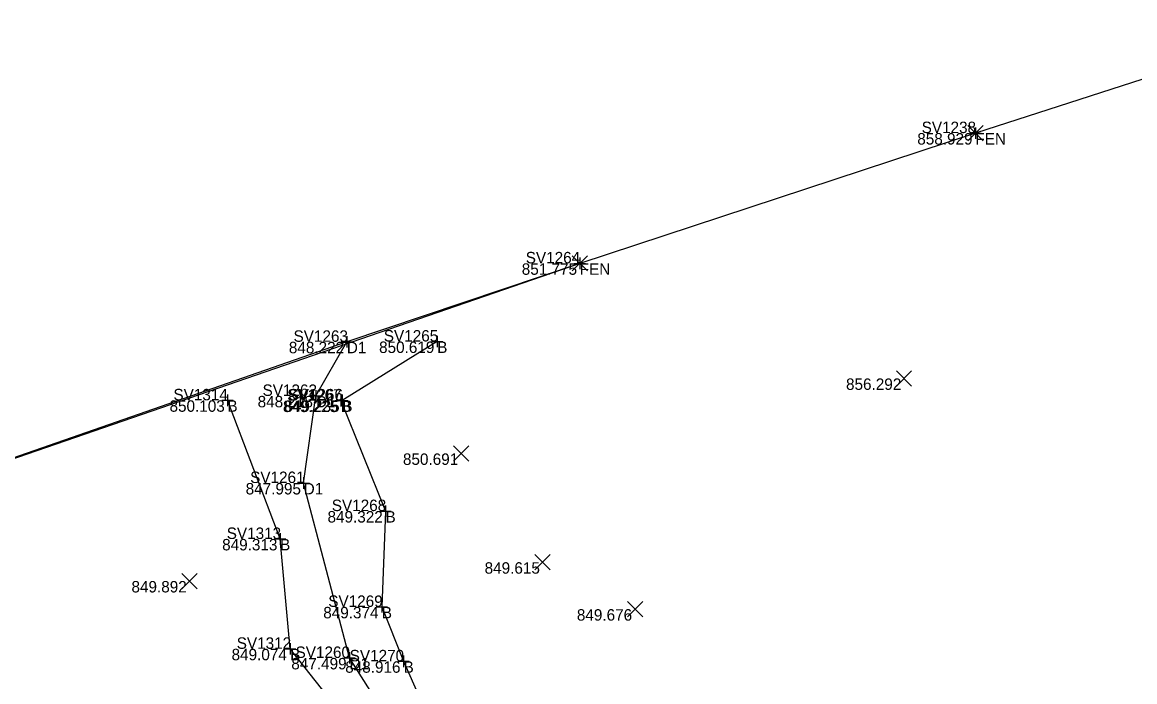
# Model space of a CAD drawing. Extents: x 2125299 to 2129212, y 713100 to 714300.
# Drawn here: x 2128258.4 to 2128355.7, y 714191.5 to 714249.1 of the extents above; entities that cross this region are included whole.
import ezdxf

# ---------------------------------------------------------------- set-up
doc = ezdxf.new("R2010")
doc.units = 0
for name, color, linetype in [('DR_X_Ditch', 7, 'Continuous'), ('DT_X_Terrain_Boundary', 7, 'Continuous'), ('RD_X_Fence', 7, 'Continuous'), ('RW_P_Esmt_TMP', 7, 'Continuous'), ('RW_X_Esmt_CH', 7, 'Continuous'), ('RW_X_Fee_WL', 7, 'Continuous'), ('SV_X_Break_Lines', 7, 'Continuous'), ('SV_X_Mon_Cells_Found', 7, 'Continuous'), ('SV_X_Text_Elevation', 7, 'Continuous')]:
    doc.layers.add(name, color=color, linetype=linetype)

msp = doc.modelspace()

# ---------------------------------------------------------------- linework, layer by layer
at = {"layer": 'DR_X_Ditch'}
msp.add_lwpolyline([(2128282.878, 714152.985), (2128282.322, 714154.568), (2128280.684, 714162.784), (2128280.715, 714165.854), (2128282.282, 714171.907), (2128284.07, 714176.901), (2128291.608, 714180.596), (2128291.656, 714186.324), (2128287.057, 714193.601), (2128283.052, 714208.887), (2128284.129, 714216.499), (2128286.829, 714221.225)], dxfattribs=at)
at = {"layer": 'DT_X_Terrain_Boundary'}
msp.add_lwpolyline([(2128442.631, 714160.201), (2128404.428, 714186.272), (2128371.881, 714249.149), (2128341.796, 714239.463), (2128307.194, 714228.082), (2128286.829, 714221.225), (2128228.864, 714201.068), (2128207.391, 714193.903), (2128150.546, 714124.176), (2128126.019, 714119.425), (2128120.141, 714107.516), (2128111.883, 714086.218), (2128106.869, 714068.79), (2128101.835, 714061.266), (2128102.404, 714047.835), (2128092.731, 714045.299), (2128083.057, 714042.765), (2128073.384, 714040.23), (2128063.71, 714037.696), (2128054.037, 714035.161), (2128044.363, 714032.627), (2128034.69, 714030.093), (2128025.016, 714027.558)], dxfattribs=at)
at = {"layer": 'RD_X_Fence'}
msp.add_lwpolyline([(2128371.881, 714249.149), (2128341.796, 714239.463), (2128307.194, 714228.082), (2128228.863, 714201.068), (2128207.391, 714193.903)], dxfattribs=at)
at = {"layer": 'SV_X_Break_Lines'}
for points in [[(2128294.731, 714221.25), (2128286.429, 714216.107), (2128286.307, 714216.085), (2128290.211, 714206.434), (2128289.886, 714198.061), (2128291.79, 714193.305), (2128293.753, 714188.829), (2128301.414, 714189.738), (2128311.099, 714187.98), (2128315.392, 714186.993), (2128315.738, 714184.367), (2128308.586, 714184.286), (2128301.154, 714185.129), (2128295.038, 714185.419), (2128293.414, 714179.277), (2128290.994, 714176.583), (2128286.414, 714175.49), (2128286.417, 714175.493), (2128286.617, 714173.173), (2128291.92, 714175.499), (2128298.034, 714172.742), (2128324.661, 714177.129), (2128340.162, 714175.773), (2128345.323, 714175.683)], [(2128281.871, 714194.398), (2128280.987, 714203.998), (2128276.385, 714216.113)], [(2128279.118, 714167.221), (2128278.774, 714174.351), (2128283.748, 714179.208), (2128288.829, 714182.513), (2128286.358, 714188.724), (2128281.871, 714194.398)]]:
    msp.add_lwpolyline(points, dxfattribs=at)
at = {"layer": 'SV_X_Mon_Cells_Found'}
for p, q in [((2128341.796, 714239.963), (2128341.796, 714238.963)), ((2128341.296, 714239.463), (2128342.296, 714239.463)), ((2128341.796, 714239.463), (2128341.796, 714239.463)), ((2128307.194, 714228.582), (2128307.194, 714227.582)), ((2128306.694, 714228.082), (2128307.694, 714228.082)), ((2128307.194, 714228.082), (2128307.194, 714228.082)), ((2128286.829, 714221.725), (2128286.829, 714220.725)), ((2128294.731, 714221.75), (2128294.731, 714220.75)), ((2128286.329, 714221.225), (2128287.329, 714221.225)), ((2128286.829, 714221.225), (2128286.829, 714221.225)), ((2128294.231, 714221.25), (2128295.231, 714221.25)), ((2128294.731, 714221.25), (2128294.731, 714221.25)), ((2128276.385, 714216.613), (2128276.385, 714215.613)), ((2128284.129, 714216.999), (2128284.129, 714215.999)), ((2128286.307, 714216.585), (2128286.307, 714215.585)), ((2128286.429, 714216.607), (2128286.429, 714215.607)), ((2128275.885, 714216.113), (2128276.885, 714216.113)), ((2128276.385, 714216.113), (2128276.385, 714216.113)), ((2128283.629, 714216.499), (2128284.629, 714216.499)), ((2128284.129, 714216.499), (2128284.129, 714216.499)), ((2128285.807, 714216.085), (2128286.807, 714216.085)), ((2128285.929, 714216.107), (2128286.929, 714216.107)), ((2128286.307, 714216.085), (2128286.307, 714216.085)), ((2128286.429, 714216.107), (2128286.429, 714216.107)), ((2128282.552, 714208.887), (2128283.552, 714208.887)), ((2128283.052, 714209.387), (2128283.052, 714208.387)), ((2128283.052, 714208.887), (2128283.052, 714208.887)), ((2128290.211, 714206.934), (2128290.211, 714205.934)), ((2128289.711, 714206.434), (2128290.711, 714206.434)), ((2128290.211, 714206.434), (2128290.211, 714206.434)), ((2128280.487, 714203.998), (2128281.487, 714203.998)), ((2128280.987, 714204.498), (2128280.987, 714203.498)), ((2128280.987, 714203.998), (2128280.987, 714203.998)), ((2128289.886, 714198.561), (2128289.886, 714197.561)), ((2128289.386, 714198.061), (2128290.386, 714198.061)), ((2128289.886, 714198.061), (2128289.886, 714198.061)), ((2128281.371, 714194.398), (2128282.371, 714194.398)), ((2128281.871, 714194.898), (2128281.871, 714193.898)), ((2128281.871, 714194.398), (2128281.871, 714194.398)), ((2128286.557, 714193.601), (2128287.557, 714193.601)), ((2128287.057, 714194.101), (2128287.057, 714193.101)), ((2128287.057, 714193.601), (2128287.057, 714193.601)), ((2128291.29, 714193.305), (2128292.29, 714193.305)), ((2128291.79, 714193.805), (2128291.79, 714192.805)), ((2128291.79, 714193.305), (2128291.79, 714193.305))]:
    msp.add_line(p, q, dxfattribs=at)
at = {"layer": 'SV_X_Text_Elevation'}
for p, q in [((2128341.129, 714238.795), (2128342.463, 714240.13)), ((2128341.129, 714240.13), (2128342.463, 714238.795)), ((2128306.527, 714227.415), (2128307.861, 714228.75)), ((2128306.527, 714228.75), (2128307.861, 714227.415)), ((2128334.887, 714217.357), (2128336.221, 714218.692)), ((2128334.887, 714218.692), (2128336.221, 714217.357)), ((2128296.149, 714210.804), (2128297.483, 714212.139)), ((2128296.149, 714212.139), (2128297.483, 714210.804)), ((2128303.28, 714201.296), (2128304.614, 714202.631)), ((2128303.28, 714202.631), (2128304.614, 714201.296)), ((2128272.4, 714199.654), (2128273.734, 714200.99)), ((2128272.4, 714200.99), (2128273.734, 714199.654)), ((2128311.379, 714197.194), (2128312.713, 714198.529)), ((2128311.379, 714198.529), (2128312.713, 714197.194))]:
    msp.add_line(p, q, dxfattribs=at)

# ---------------------------------------------------------------- texts
at = {"layer": 'RW_P_Esmt_TMP'}
for s, p in [('FEN', (2128341.796, 714238.463)), ('FEN', (2128307.194, 714227.082)), ('D1', (2128286.829, 714220.225)), ('B', (2128294.731, 714220.25)), ('B', (2128276.385, 714215.113)), ('D1', (2128284.129, 714215.499)), ('B', (2128286.307, 714215.085)), ('B', (2128286.429, 714215.107)), ('D1', (2128283.052, 714207.887)), ('B', (2128290.211, 714205.434)), ('B', (2128280.987, 714202.998)), ('B', (2128289.886, 714197.061)), ('B', (2128281.871, 714193.398)), ('D1', (2128287.057, 714192.601)), ('B', (2128291.79, 714192.305))]:
    msp.add_text(s, height=1, dxfattribs=at).set_placement(p)
at = {"layer": 'RW_X_Esmt_CH'}
for s, p in [('SV1238', (2128337.097, 714239.463)), ('SV1264', (2128302.474, 714228.082)), ('SV1263', (2128282.167, 714221.225)), ('SV1265', (2128290.062, 714221.25)), ('SV1314', (2128271.665, 714216.113)), ('SV1262', (2128279.458, 714216.499)), ('SV1267', (2128281.613, 714216.085)), ('SV1266', (2128281.727, 714216.107)), ('SV1261', (2128278.372, 714208.887)), ('SV1268', (2128285.512, 714206.434)), ('SV1313', (2128276.325, 714203.998)), ('SV1269', (2128285.204, 714198.061)), ('SV1312', (2128277.2, 714194.398)), ('SV1260', (2128282.345, 714193.601)), ('SV1270', (2128287.078, 714193.305))]:
    msp.add_text(s, height=1, dxfattribs=at).set_placement(p)
at = {"layer": 'RW_X_Fee_WL'}
for s, p in [('858.929', (2128336.712, 714238.463)), ('858.929', (2128336.712, 714238.463)), ('851.775', (2128302.124, 714227.082)), ('851.775', (2128302.124, 714227.082)), ('848.222', (2128281.756, 714220.225)), ('850.619', (2128289.647, 714220.25)), ('856.292', (2128330.481, 714217.024)), ('850.103', (2128271.321, 714215.113)), ('848.218', (2128279.029, 714215.499)), ('849.225', (2128281.237, 714215.085)), ('849.235', (2128281.359, 714215.107)), ('850.691', (2128291.734, 714210.471)), ('847.995', (2128277.982, 714207.887)), ('849.322', (2128285.138, 714205.434)), ('849.313', (2128275.923, 714202.998)), ('849.615', (2128298.877, 714200.963)), ('849.892', (2128267.994, 714199.322)), ('849.374', (2128284.764, 714197.061)), ('849.676', (2128306.942, 714196.862)), ('849.074', (2128276.749, 714193.398)), ('847.499', (2128281.973, 714192.601)), ('848.916', (2128286.686, 714192.305))]:
    msp.add_text(s, height=1, dxfattribs=at).set_placement(p)

doc.saveas('drawing.dxf')
